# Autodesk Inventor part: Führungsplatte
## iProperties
Company: HERDT-Verlag
Created: 2006-01
Part Number: Führungsplatte
Material: 1.0050 St 50-2
Document SubType Name: Modeling
Designer: Eichenseer
Project: Inventor 11 - Grundkurs
Checked By: G. Lehmann
Engr Approved By: M. Grouls
Description: DIN 1017 110x22x85
Engineer: Käs
Author: P. Tropf
Subject: Inventor 10 - Grundkurs
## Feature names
1. Grundkörper [Extrusion]
2. Führungsnut [Extrusion]
3. Zentrierung [Extrusion]
4. Bohrung1 [Hole]
